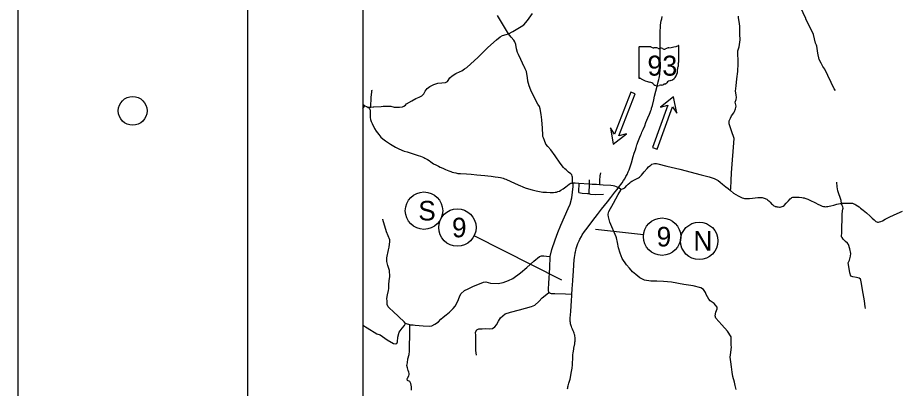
# Model space of a CAD drawing. Extents: x 2025369 to 2161369, y 549489 to 637489.
# Drawn here: x 2025369 to 2056140, y 600839 to 613730 of the extents above; entities that cross this region are included whole.
import ezdxf

# ---------------------------------------------------------------- set-up
doc = ezdxf.new("R2010")
doc.units = 0
for name, color, linetype in [('GM_X_County_Road', 7, 'Continuous'), ('GM_X_State_Route', 7, 'Continuous'), ('GM_X_State_Shield', 7, 'Continuous'), ('GM_X_Township_Road', 7, 'Continuous'), ('GM_X_Township_Subdivision', 7, 'Continuous'), ('SH_Border', 7, 'Continuous'), ('SH_Cut_Line', 7, 'Continuous'), ('SH_Text', 7, 'Continuous')]:
    doc.layers.add(name, color=color, linetype=linetype)

msp = doc.modelspace()

# ---------------------------------------------------------------- linework, layer by layer
at = {"layer": 'GM_X_County_Road'}
for points in [[(2052787, 613697), (2052219, 614921), (2052168, 614999), (2052110, 615089), (2052054, 615189), (2052023, 615276), (2051957, 615408), (2051872, 615497), (2051782, 615521), (2051680, 615533), (2051587, 615550), (2051527, 615570), (2051455, 615644), (2051345, 615790)], [(2037754, 610632), (2038010, 610638), (2038079, 610647), (2038344, 610649), (2038461, 610620), (2038563, 610615), (2038654, 610617), (2038752, 610631), (2038806, 610658), (2038853, 610686), (2038893, 610728), (2039079, 610841), (2039219, 610915), (2039337, 610964), (2039427, 611012), (2039496, 611080), (2039540, 611172), (2039612, 611270), (2039710, 611339), (2039840, 611409), (2039988, 611453), (2040128, 611466), (2040254, 611480), (2040316, 611508), (2040406, 611641), (2040481, 611709), (2040615, 611787), (2040763, 611864), (2040821, 611884), (2040907, 611952), (2040989, 611996), (2041392, 612359), (2041728, 612695), (2042020, 612958), (2042146, 613064), (2042235, 613109), (2042363, 613142), (2042444, 613174), (2042588, 613252), (2042768, 613349), (2042880, 613419), (2042974, 613481), (2043102, 613634), (2043277, 613880)], [(2042444, 613174), (2042056, 613803)], [(2053154, 612770), (2053154, 612771), (2053125, 612839), (2053045, 613141), (2052787, 613696), (2052787, 613697)], [(2053814, 611198), (2053770, 611260), (2053441, 611938), (2053376, 612033), (2053314, 612145), (2053253, 612275), (2053202, 612500), (2053169, 612734), (2053154, 612770)], [(2037369, 610718), (2037449, 610668)], [(2037369, 610567), (2037449, 610668), (2037500, 610643)], [(2037500, 610643), (2037526, 610630), (2037562, 610619), (2037608, 610615), (2037649, 610623)], [(2037526, 610630), (2037559, 610611), (2037583, 610596), (2037608, 610571), (2037622, 610542), (2037632, 610509), (2037632, 610416)], [(2037649, 610623), (2037649, 610623), (2037733, 610631), (2037754, 610632)], [(2037632, 610416), (2037633, 610259), (2037642, 610191), (2037662, 610119), (2037694, 610045), (2037779, 609871), (2037836, 609781), (2037928, 609664), (2038004, 609579), (2038075, 609512), (2038160, 609444), (2038332, 609332), (2038515, 609226), (2038599, 609183), (2038726, 609127), (2038816, 609091), (2038911, 609059), (2039095, 609004), (2039195, 608975), (2039298, 608940), (2039378, 608912), (2039435, 608888), (2039491, 608863), (2039532, 608843), (2039582, 608817), (2039623, 608792), (2039676, 608758), (2039736, 608717), (2039781, 608686), (2039837, 608651), (2039910, 608612), (2040008, 608563), (2040070, 608533), (2040154, 608496), (2040253, 608452), (2040361, 608407), (2040431, 608379), (2040484, 608360), (2040539, 608343), (2040605, 608328), (2040682, 608316), (2040771, 608311), (2040985, 608296), (2041147, 608283), (2041340, 608266), (2041616, 608238), (2041719, 608228), (2041836, 608214), (2041975, 608193), (2042080, 608179), (2042163, 608166), (2042213, 608157), (2042254, 608146), (2042306, 608129), (2042354, 608110), (2042673, 607965), (2042853, 607882), (2042921, 607854), (2042966, 607835), (2043060, 607804), (2043264, 607747), (2043406, 607710), (2043522, 607682), (2043580, 607670), (2043641, 607663), (2043759, 607658), (2043893, 607654), (2044003, 607655), (2044062, 607660), (2044106, 607666), (2044163, 607679), (2044212, 607698), (2044261, 607727), (2044338, 607775), (2044436, 607846), (2044497, 607894), (2044557, 607939), (2044586, 607958), (2044607, 607969), (2044618, 607972)], [(2046768, 608061), (2046783, 608069), (2046851, 608104), (2046922, 608141), (2046960, 608161), (2046995, 608184), (2047019, 608204), (2047065, 608250), (2047166, 608373), (2047260, 608484), (2047314, 608543), (2047354, 608580), (2047390, 608606), (2047431, 608630), (2047475, 608645), (2047524, 608653), (2047595, 608654), (2047640, 608648), (2047953, 608567), (2048398, 608457), (2049138, 608266), (2049424, 608189), (2049530, 608159), (2049591, 608139), (2049642, 608119), (2049665, 608107), (2049690, 608094), (2049732, 608065), (2049803, 608012), (2049891, 607942), (2050000, 607852), (2050082, 607784), (2050160, 607719), (2050272, 607627), (2050350, 607577), (2050435, 607528), (2050505, 607494), (2050573, 607465), (2050610, 607452), (2050653, 607443), (2050702, 607439), (2050744, 607440), (2050829, 607446), (2050925, 607457), (2051025, 607468), (2051114, 607473), (2051213, 607475), (2051263, 607473), (2051299, 607466), (2051339, 607455), (2051369, 607444), (2051397, 607430), (2051428, 607412), (2051465, 607386), (2051500, 607355), (2051547, 607308), (2051595, 607258), (2051624, 607230), (2051649, 607207), (2051675, 607189), (2051702, 607174), (2051722, 607166), (2051748, 607158), (2051777, 607151), (2051816, 607146), (2051866, 607143), (2051897, 607145), (2051927, 607151), (2051962, 607160), (2051994, 607176), (2052027, 607201), (2052097, 607274), (2052177, 607365), (2052240, 607431), (2052269, 607454), (2052298, 607471), (2052327, 607482), (2052360, 607490), (2052402, 607492), (2052470, 607491), (2052553, 607484), (2052645, 607473), (2052686, 607467), (2052728, 607459), (2052753, 607452), (2052787, 607442), (2052849, 607421), (2052926, 607385), (2053116, 607289), (2053206, 607242), (2053277, 607206), (2053309, 607192), (2053351, 607176), (2053402, 607162), (2053430, 607157), (2053462, 607156), (2053505, 607157), (2053545, 607160), (2053601, 607169), (2053654, 607183), (2053760, 607212), (2053868, 607242), (2053978, 607265), (2054030, 607272), (2054065, 607276), (2054136, 607280), (2054280, 607284), (2054343, 607284), (2054382, 607280), (2054409, 607274), (2054449, 607260), (2054488, 607243), (2054528, 607221), (2054577, 607188), (2054638, 607147), (2054685, 607110), (2054777, 607037), (2054893, 606937), (2055025, 606824), (2055095, 606759), (2055156, 606696), (2055193, 606661), (2055224, 606640), (2055252, 606627), (2055281, 606620), (2055307, 606621), (2055349, 606626), (2055393, 606640), (2055447, 606663), (2055539, 606718), (2055677, 606797), (2055854, 606872), (2056143, 607004)], [(2046270, 607818), (2046358, 607769), (2046406, 607772), (2046445, 607784), (2046485, 607815), (2046560, 607892), (2046608, 607942), (2046657, 607988), (2046695, 608018), (2046733, 608042), (2046768, 608061)], [(2044647, 604104), (2044428, 604108), (2044056, 604128), (2043938, 604129), (2043907, 604134), (2043880, 604149), (2043850, 604171), (2043839, 604191), (2043838, 604214), (2043838, 604282), (2043850, 604501), (2043876, 605032), (2043887, 605421), (2043943, 605662), (2044062, 606004), (2044153, 606254), (2044267, 606519), (2044520, 607095), (2044582, 607242), (2044641, 607465), (2044664, 607662), (2044685, 607860), (2044691, 607926), (2044684, 607957), (2044670, 607983)], [(2044618, 607972), (2044638, 607977), (2044670, 607983), (2044712, 607986), (2044764, 607986), (2044891, 607978), (2045250, 607953), (2045357, 607945), (2045503, 607937), (2045611, 607929), (2045738, 607920), (2046003, 607901), (2046079, 607893), (2046129, 607882), (2046192, 607858), (2046270, 607818)]]:
    msp.add_lwpolyline(points, dxfattribs=at)
at = {"layer": 'GM_X_State_Route'}
for points in [[(2046910, 609302), (2046919, 609329), (2046944, 609401), (2047010, 609577), (2047040, 609650), (2047064, 609706), (2047084, 609752), (2047123, 609845), (2047178, 609973), (2047223, 610081), (2047293, 610243), (2047351, 610375), (2047372, 610427), (2047397, 610501), (2047411, 610547), (2047420, 610581), (2047447, 610681), (2047493, 610871), (2047525, 610995), (2047571, 611179), (2047613, 611349), (2047649, 611498), (2047668, 611579), (2047678, 611622), (2047689, 611680), (2047701, 611752), (2047708, 611819), (2047712, 611878), (2047715, 611942), (2047717, 612123), (2047720, 612353), (2047718, 612790), (2047718, 613072), (2047719, 613222), (2047721, 613298), (2047723, 613363), (2047726, 613416), (2047729, 613457), (2047734, 613501), (2047738, 613530), (2047743, 613562), (2047756, 613626), (2047770, 613692), (2047786, 613767)], [(2044632, 603893), (2044642, 604054), (2044647, 604104), (2044660, 604304), (2044679, 604578), (2044693, 604777), (2044700, 604899), (2044717, 605142), (2044730, 605298), (2044740, 605395), (2044746, 605444), (2044749, 605468), (2044755, 605511), (2044762, 605548), (2044770, 605583), (2044782, 605634), (2044799, 605700), (2044830, 605802), (2044855, 605870), (2044895, 605965), (2044926, 606030), (2044975, 606123), (2045005, 606175), (2045080, 606289), (2045128, 606356), (2045242, 606502), (2045376, 606676), (2045537, 606882), (2045682, 607068), (2045780, 607193), (2045884, 607325), (2045997, 607471), (2046145, 607656), (2046217, 607750), (2046270, 607818), (2046396, 607991), (2046447, 608068), (2046486, 608130), (2046526, 608202), (2046565, 608277), (2046609, 608373), (2046635, 608434), (2046677, 608547), (2046719, 608678), (2046781, 608902), (2046817, 609021), (2046856, 609138), (2046880, 609213), (2046910, 609302)], [(2044494, 600817), (2044500, 600852), (2044507, 600887), (2044517, 600929), (2044542, 601017), (2044582, 601160), (2044595, 601218), (2044625, 601368), (2044653, 601535), (2044659, 601571), (2044664, 601619), (2044668, 601668), (2044670, 601720), (2044674, 601862), (2044681, 601972), (2044683, 602014), (2044688, 602060), (2044701, 602146), (2044709, 602199), (2044715, 602232), (2044743, 602388), (2044752, 602441), (2044756, 602484), (2044758, 602551), (2044757, 602610), (2044753, 602655), (2044746, 602692), (2044739, 602716), (2044727, 602753), (2044711, 602796), (2044694, 602839), (2044669, 602897), (2044649, 602944), (2044632, 602987), (2044622, 603015), (2044613, 603043), (2044603, 603084), (2044595, 603125), (2044592, 603158), (2044590, 603186), (2044589, 603225), (2044590, 603279), (2044605, 603509), (2044618, 603712), (2044631, 603884), (2044632, 603893)]]:
    msp.add_lwpolyline(points, dxfattribs=at)
at = {"layer": 'GM_X_State_Shield'}
for p, q in [((2046974, 612696), (2046974, 611640)), ((2047396, 612714), (2046988, 612714)), ((2048367, 612188), (2048367, 612741)), ((2048366, 612188), (2048367, 612188))]:
    msp.add_line(p, q, dxfattribs=at)
for centre, radius, start, end in [((2046990, 612698), 16.1, 98.1301, 188.1301), ((2047493, 612837), 156, 231.6195, 271.1119), ((2047545, 612121), 562, 80.4867, 94.9883), ((2047672, 612704), 45.1, 219.7921, 297.1024), ((2047738, 612582), 93.8, 54.4667, 119.1411), ((2047860, 612749), 113, 233.8562, 294.8282), ((2048059, 612392), 297, 97.3462, 120.7689), ((2047871, 614155), 1476, 275.8445, 288.9065), ((2048351, 612743), 15.5, 351.8621, 97.738), ((2048363, 612147), 24, 107.944, 210.337), ((2048210, 612077), 144, 340.033, 23.6496), ((2048350, 612186), 16.6, 289.6038, 7.7341), ((2047953, 611886), 369, 292.3089, 8.9858), ((2048422, 611957), 105, 136.8065, 186.9296), ((2046990, 611637), 16.3, 171.9584, 258.3066), ((2046993, 611745), 124, 267.339, 280.6039), ((2047018, 611579), 44.8, 29.7484, 93.2717), ((2047584, 612528), 1066, 240.4129, 257.1985), ((2047266, 611165), 334, 47.1842, 75.836), ((2047853, 611537), 119, 282.8732, 323.2771), ((2048109, 611343), 202, 94.4031, 142.5768), ((2047627, 611573), 212, 230.7004, 286.2918), ((2047749, 611208), 174, 85.6951, 111.2099), ((2047764, 611494), 113, 268.777, 315.5493), ((2047866, 611392), 31.8, 65.7517, 132.6484)]:
    msp.add_arc(centre, radius, start, end, dxfattribs=at)
at = {"layer": 'GM_X_Township_Road'}
for points in [[(2050160, 607719), (2050172, 607787), (2050183, 608070), (2050200, 608329), (2050293, 609533), (2050196, 609793), (2050122, 610038), (2050118, 610142), (2050159, 610238), (2050198, 610320), (2050276, 610418), (2050304, 610462), (2050340, 610558), (2050355, 610656), (2050331, 610790), (2050362, 610890), (2050376, 610958), (2050366, 611044), (2050339, 611179), (2050366, 611365), (2050385, 611607), (2050422, 611855), (2050435, 612137), (2050417, 612580), (2050463, 612722), (2050500, 612962), (2050487, 613161), (2050487, 613301), (2050486, 613435), (2050469, 613597), (2050447, 613723), (2050441, 613780)], [(2044670, 607983), (2044672, 608182), (2044661, 608221), (2044642, 608262), (2044605, 608301), (2044533, 608362), (2044444, 608433), (2044403, 608472), (2044351, 608517), (2044242, 608674), (2044061, 608921), (2043913, 609128), (2043810, 609248), (2043741, 609331), (2043689, 609463), (2043655, 609546), (2043641, 609593), (2043637, 609647), (2043624, 609888), (2043606, 610182), (2043583, 610366), (2043540, 610564), (2043516, 610636), (2043460, 610721), (2043278, 611078), (2043217, 611208), (2043165, 611361), (2043118, 611525), (2043098, 611649), (2043078, 611777), (2043064, 611853), (2043026, 611947), (2042995, 612013), (2042987, 612024), (2042869, 612271), (2042788, 612444), (2042754, 612518), (2042723, 612644), (2042694, 612792), (2042664, 612891), (2042622, 612954), (2042536, 613050), (2042444, 613174)], [(2037649, 610623), (2037665, 610967), (2037684, 611141), (2037692, 611195), (2037705, 611204)], [(2045925, 606942), (2045935, 606986), (2046092, 607279), (2046259, 607582), (2046350, 607730), (2046358, 607769)], [(2054072, 607070), (2054082, 607102), (2054071, 607146), (2054051, 607203), (2054030, 607272), (2054009, 607376), (2053893, 607710), (2053870, 607850), (2053865, 608004)], [(2050362, 600793), (2050330, 600938), (2050298, 601054), (2050248, 601253), (2050218, 601400), (2050193, 601589), (2050170, 601757), (2050155, 601926), (2050164, 602006), (2050185, 602173), (2050193, 602277), (2050186, 602330), (2050190, 602462), (2050191, 602552), (2050181, 602630), (2050062, 602826), (2049866, 603048), (2049752, 603164), (2049648, 603277), (2049626, 603364), (2049658, 603486), (2049696, 603603), (2049705, 603661), (2049646, 603726), (2049597, 603787), (2049522, 603834), (2049461, 603877), (2049406, 603944), (2049367, 604017), (2049315, 604096), (2049292, 604166), (2049265, 604211), (2049222, 604276), (2049133, 604331), (2048866, 604401), (2048546, 604451), (2048108, 604532), (2047837, 604554), (2047599, 604560), (2047392, 604563), (2047177, 604599), (2047009, 604678), (2046867, 604796), (2046757, 604888), (2046649, 605016), (2046551, 605136), (2046399, 605352), (2046324, 605544), (2046273, 605723), (2046236, 605910), (2046201, 606067), (2046182, 606113), (2045969, 606621), (2045944, 606709), (2045920, 606806), (2045909, 606874), (2045914, 606894), (2045925, 606942)], [(2054112, 605991), (2054080, 606023), (2054043, 606086), (2054027, 606113), (2054031, 606273), (2054048, 606890), (2054054, 607008), (2054072, 607070)], [(2038857, 603091), (2038809, 603149), (2038432, 603510), (2038303, 603627), (2038258, 603676), (2038224, 603757), (2038222, 603872), (2038210, 603965), (2038235, 604085), (2038264, 604246), (2038280, 604315), (2038280, 604444), (2038290, 604577), (2038317, 604730), (2038303, 604934), (2038247, 605108), (2038213, 605255), (2038210, 605377), (2038272, 605657), (2038295, 605752), (2038308, 605943), (2038318, 606003), (2038198, 606276), (2038070, 606705), (2038066, 606718)], [(2054860, 603614), (2054857, 603631), (2054852, 603669), (2054820, 603880), (2054782, 604142), (2054746, 604337), (2054721, 604481), (2054698, 604597), (2054680, 604639), (2054644, 604673), (2054548, 604694), (2054422, 604718), (2054353, 604736), (2054313, 604853), (2054292, 605005), (2054261, 605205), (2054299, 605299), (2054334, 605439), (2054354, 605525), (2054313, 605694), (2054263, 605842), (2054232, 605886), (2054162, 605941), (2054112, 605991)], [(2039014, 603043), (2039127, 603049), (2039198, 603040), (2039330, 603028), (2039469, 603015), (2039693, 602998), (2039769, 603012), (2039879, 603067), (2040005, 603151), (2040086, 603246), (2040163, 603314), (2040268, 603393), (2040394, 603491), (2040511, 603609), (2040585, 603700), (2040683, 603867), (2040738, 604018), (2040783, 604129), (2040913, 604237), (2041044, 604299), (2041205, 604377), (2041574, 604529), (2041658, 604538), (2041818, 604501), (2042079, 604479), (2042251, 604520), (2042436, 604593), (2042591, 604663), (2042854, 604861), (2043080, 605046), (2043323, 605260), (2043518, 605421), (2043584, 605450), (2043666, 605450), (2043759, 605437), (2043887, 605421)], [(2041328, 601989), (2041304, 602153), (2041300, 602675), (2041298, 602790), (2041343, 602871), (2041410, 602908), (2041530, 602910), (2041648, 602920), (2041783, 602912), (2041879, 602924), (2041966, 602973), (2042029, 603048), (2042095, 603177), (2042163, 603292), (2042331, 603428), (2042511, 603491), (2042824, 603572), (2043247, 603681), (2043356, 603729), (2043500, 603863), (2043618, 603982), (2043711, 604064), (2043850, 604171)], [(2037369, 603036), (2037525, 602939), (2037864, 602739), (2037975, 602704), (2038224, 602526), (2038443, 602403), (2038515, 602384), (2038557, 602396), (2038581, 602454), (2038596, 602612), (2038639, 602792), (2038746, 602930), (2038818, 603022), (2038857, 603091)], [(2039062, 600772), (2039068, 600894), (2039061, 600952), (2039041, 601011), (2039008, 601080), (2038931, 601116), (2038918, 601164), (2038924, 601188), (2038969, 601267), (2038986, 601317), (2038991, 601349), (2038978, 601403), (2038951, 601462), (2038924, 601546), (2038910, 601629), (2038925, 601724), (2038943, 601860), (2038986, 602014), (2039000, 602136), (2039000, 602270), (2039007, 602718), (2039014, 603043), (2038893, 603080), (2038857, 603091)]]:
    msp.add_lwpolyline(points, dxfattribs=at)
at = {"layer": 'GM_X_Township_Subdivision'}
for points in [[(2045247, 608087), (2045250, 607953), (2045231, 607610)], [(2045636, 608328), (2045623, 608225), (2045611, 608068), (2045611, 607929)], [(2044891, 607978), (2044878, 607669)], [(2044878, 607669), (2044886, 607650), (2045006, 607629), (2045185, 607614)], [(2045185, 607614), (2045231, 607610), (2045256, 607602), (2045291, 607595), (2045464, 607583), (2045742, 607588)]]:
    msp.add_lwpolyline(points, dxfattribs=at)
at = {"layer": 'SH_Border'}
msp.add_lwpolyline([(2033369, 635489), (2159369, 635489), (2159369, 551489), (2033369, 551489)], close=True, dxfattribs=at)
msp.add_circle((2029369, 610489), 500, dxfattribs=at)
at = {"layer": 'SH_Cut_Line'}
msp.add_lwpolyline([(2025369, 549489), (2161369, 549489), (2161369, 637489), (2025369, 637489)], close=True, dxfattribs=at)
at = {"layer": 'SH_Text'}
for p, q in [((2045469, 606374), (2047137, 606186)), ((2044294, 604599), (2041243, 606139))]:
    msp.add_line(p, q, dxfattribs=at)
msp.add_lwpolyline([(2037369, 631489), (2037369, 571561), (2092420, 571561), (2092420, 631489)], dxfattribs=at)
for points in [[(2046850, 611084), (2046695, 611144), (2046129, 609679), (2045984, 609904), (2046084, 609330), (2046544, 609688), (2046285, 609619)], [(2047453, 609210), (2047610, 609153), (2048143, 610631), (2048293, 610408), (2048181, 610980), (2047729, 610612), (2047987, 610687)]]:
    msp.add_lwpolyline(points, close=True, dxfattribs=at)
for centre in [(2039502, 607017), (2040663, 606432), (2047783, 606113), (2049075, 605967)]:
    msp.add_circle(centre, 650, dxfattribs=at)

# ---------------------------------------------------------------- texts
at = {"layer": 'GM_X_State_Shield'}
msp.add_text('93', height=696.1, dxfattribs=at).set_placement((2047275, 611714))
at = {"layer": 'SH_Text'}
for s, p in [('S', (2039304, 606677)), ('9', (2040476, 606092)), ('9', (2047595, 605773)), ('N', (2048874, 605627))]:
    msp.add_text(s, height=680, dxfattribs=at).set_placement(p)

doc.saveas('drawing.dxf')
